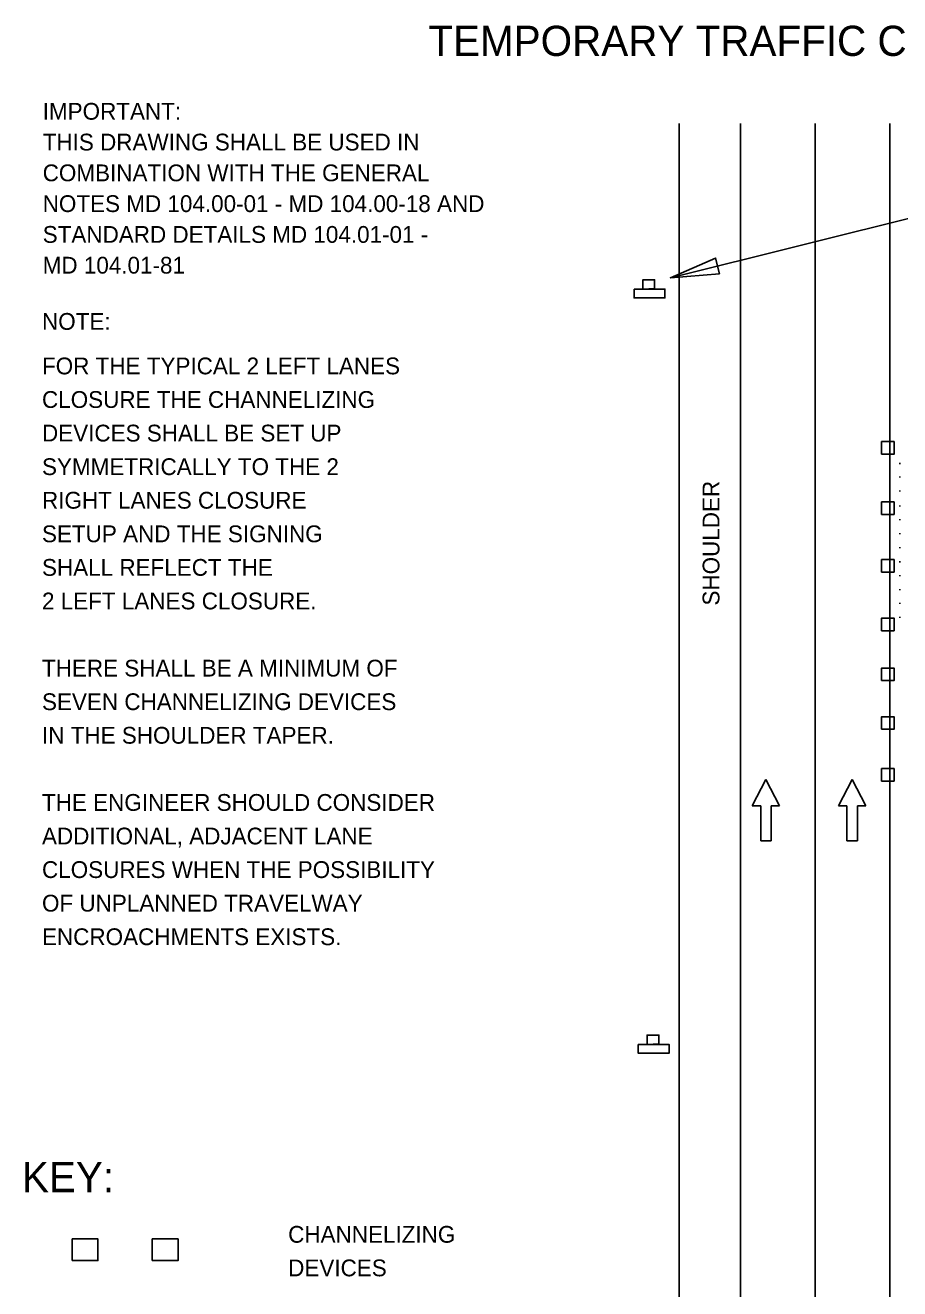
# Model space of a CAD drawing. Extents: x 1531.3 to 1538.6, y 1529.6 to 1539.7.
# Drawn here: x 1531.302 to 1534.427, y 1535.19 to 1539.705 of the extents above; entities that cross this region are included whole.
import ezdxf

# ---------------------------------------------------------------- set-up
doc = ezdxf.new("R2010")
doc.units = 0
for name, color, linetype in [('DETL-DIMS', 7, 'Continuous'), ('DETL-LINE', 7, 'Continuous'), ('DETL-NOTE', 7, 'Continuous'), ('DETL-TITL', 7, 'Continuous'), ('USER-BORD', 7, 'Continuous')]:
    doc.layers.add(name, color=color, linetype=linetype)

# ---------------------------------------------------------------- blocks, each defined once
blk = doc.blocks.new('DIR4')
at = {"layer": 'USER-BORD'}
for p, q in [((0, 0.0001), (-0.0034, -0.0048)), ((0, 0.0001), (0.0034, -0.0048)), ((-0.0034, -0.0048), (-0.0013, -0.0048)), ((-0.0013, -0.0113), (-0.0013, -0.0048)), ((0.0034, -0.0048), (0.0013, -0.0048)), ((0.0013, -0.0113), (0.0013, -0.0048)), ((-0.0001, -0.0113), (-0.0013, -0.0113)), ((-0.0001, -0.0113), (0.0001, -0.0113)), ((0.0001, -0.0113), (0.0013, -0.0113))]:
    blk.add_line(p, q, dxfattribs=at)
blk = doc.blocks.new('SIGN15')
at = {"layer": 'USER-BORD'}
for points in [[(-0.0013, 0.0018), (0.0011, 0.0019), (0.0011, 0.0037), (-0.0013, 0.0037)], [(-0.0031, 0.0018), (-0.0031, 0), (0.0032, 0), (0.0032, 0.0018)]]:
    blk.add_lwpolyline(points, close=True, dxfattribs=at)

msp = doc.modelspace()

# ---------------------------------------------------------------- linework, layer by layer
at = {"layer": 'DETL-DIMS'}
msp.add_line((1533.6072, 1538.8025), (1535.4261, 1539.2559), dxfattribs=at)
msp.add_lwpolyline([(1533.7824, 1538.8171), (1533.7685, 1538.8732), (1533.6072, 1538.8025)], close=True, dxfattribs=at)
at = {"layer": 'DETL-LINE'}
for p, q in [((1533.6384, 1539.3543), (1533.6384, 1531.4117)), ((1533.8574, 1539.3543), (1533.8574, 1531.4117)), ((1534.1244, 1539.3543), (1534.1244, 1531.4117)), ((1534.3913, 1539.3543), (1534.3913, 1531.4117))]:
    msp.add_line(p, q, dxfattribs=at)
for points in [[(1534.1244, 1539.3543), (1534.1244, 1539.2981)], [(1534.3913, 1539.3543), (1534.3913, 1539.2981)], [(1534.1244, 1538.9606), (1534.1244, 1538.9043)], [(1534.3913, 1538.9606), (1534.3913, 1538.9043)], [(1534.1244, 1538.9043), (1534.1244, 1538.8481)], [(1534.3913, 1538.9043), (1534.3913, 1538.8481)], [(1534.1244, 1538.5106), (1534.1244, 1538.4543)], [(1534.3913, 1538.5106), (1534.3913, 1538.4543)], [(1534.1244, 1538.4543), (1534.1244, 1538.3981)], [(1534.3913, 1538.4543), (1534.3913, 1538.3981)], [(1534.4267, 1538.1407), (1534.4267, 1538.1369)], [(1534.4267, 1538.0925), (1534.4267, 1538.0887)], [(1534.1244, 1538.0606), (1534.1244, 1538.0043)], [(1534.4267, 1538.0429), (1534.4267, 1538.0391)], [(1534.1244, 1538.0043), (1534.1244, 1537.9481)], [(1534.3913, 1538.0043), (1534.3913, 1537.9481)], [(1534.4267, 1537.9893), (1534.4267, 1537.9855)], [(1534.4267, 1537.9397), (1534.4267, 1537.9359)], [(1534.4267, 1537.8898), (1534.4267, 1537.886)], [(1534.4267, 1537.8402), (1534.4267, 1537.8364)], [(1534.4267, 1537.7893), (1534.4267, 1537.7855)], [(1534.4267, 1537.7397), (1534.4267, 1537.7359)], [(1534.4267, 1537.6903), (1534.4267, 1537.6865)], [(1534.4267, 1537.6407), (1534.4267, 1537.6369)], [(1534.1244, 1537.6106), (1534.1244, 1537.5543)], [(1534.3913, 1537.6106), (1534.3913, 1537.5543)], [(1534.4267, 1537.5907), (1534.4267, 1537.5869)], [(1534.1244, 1537.5543), (1534.1244, 1537.4981)], [(1534.3913, 1537.5543), (1534.3913, 1537.4981)], [(1534.1244, 1537.1606), (1534.1244, 1537.1043)], [(1534.3913, 1537.1606), (1534.3913, 1537.1043)], [(1534.1244, 1537.1043), (1534.1244, 1537.0481)], [(1534.3913, 1537.1043), (1534.3913, 1537.0481)], [(1534.1244, 1536.7106), (1534.1244, 1536.6543)], [(1534.1244, 1536.6543), (1534.1244, 1536.5981)], [(1534.1244, 1536.2606), (1534.1244, 1536.2043)], [(1534.3913, 1536.2606), (1534.3913, 1536.2043)], [(1534.1244, 1536.2043), (1534.1244, 1536.1481)], [(1534.3913, 1536.2043), (1534.3913, 1536.1481)], [(1534.1244, 1535.8106), (1534.1244, 1535.7543)], [(1534.3913, 1535.8106), (1534.3913, 1535.7543)], [(1534.1244, 1535.7543), (1534.1244, 1535.6981)], [(1534.3913, 1535.7543), (1534.3913, 1535.6981)], [(1534.1244, 1535.3606), (1534.1244, 1535.3043)], [(1534.3913, 1535.3606), (1534.3913, 1535.3043)], [(1534.1244, 1535.3043), (1534.1244, 1535.2481)], [(1534.3913, 1535.3043), (1534.3913, 1535.2481)]]:
    msp.add_lwpolyline(points, dxfattribs=at)
for points in [[(1534.3618, 1538.1721), (1534.4066, 1538.1721), (1534.4066, 1538.2169), (1534.3618, 1538.2169)], [(1534.3618, 1537.957), (1534.4066, 1537.957), (1534.4066, 1538.0018), (1534.3618, 1538.0018)], [(1534.3618, 1537.7506), (1534.4066, 1537.7506), (1534.4066, 1537.7954), (1534.3618, 1537.7954)], [(1534.3618, 1537.5414), (1534.4066, 1537.5414), (1534.4066, 1537.5862), (1534.3618, 1537.5862)], [(1534.3618, 1537.3628), (1534.4066, 1537.3628), (1534.4066, 1537.4076), (1534.3618, 1537.4076)], [(1534.3618, 1537.189), (1534.4066, 1537.189), (1534.4066, 1537.2338), (1534.3618, 1537.2338)], [(1534.3618, 1537.0038), (1534.4066, 1537.0038), (1534.4066, 1537.0486), (1534.3618, 1537.0486)], [(1531.4695, 1535.2899), (1531.4695, 1535.3677), (1531.5616, 1535.3677), (1531.5616, 1535.2899)], [(1531.7556, 1535.2899), (1531.7556, 1535.3677), (1531.8477, 1535.3677), (1531.8477, 1535.2899)]]:
    msp.add_lwpolyline(points, close=True, dxfattribs=at)

# ---------------------------------------------------------------- block references
for name, p, xscale, yscale in [('SIGN15', (1533.5315, 1538.7306), 17.523809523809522, 17.523809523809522), ('DIR4', (1533.9486, 1537.0074), 14.399999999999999, 19.2), ('DIR4', (1534.2568, 1537.0074), 14.399999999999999, 19.2), ('SIGN15', (1533.5466, 1536.0311), 17.523809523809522, 17.523809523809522)]:
    msp.add_blockref(name, p, dxfattribs=dict(at, xscale=xscale, yscale=yscale))

# ---------------------------------------------------------------- texts
at = {"layer": 'DETL-NOTE'}
for s, p in [('IMPORTANT:', (1531.3641, 1539.3675)), ('THIS DRAWING SHALL BE USED IN', (1531.3641, 1539.2575)), ('COMBINATION WITH THE GENERAL', (1531.3641, 1539.1475)), ('NOTES MD 104.00-01 - MD 104.00-18 AND', (1531.3641, 1539.0375)), ('STANDARD DETAILS MD 104.01-01 -', (1531.3641, 1538.9275)), ('MD 104.01-81', (1531.3641, 1538.8175)), ('NOTE:', (1531.3616, 1538.6166)), ('FOR THE TYPICAL 2 LEFT LANES', (1531.3616, 1538.4575)), ('CLOSURE THE CHANNELIZING', (1531.3616, 1538.3375)), ('DEVICES SHALL BE SET UP', (1531.3616, 1538.2175)), ('SYMMETRICALLY TO THE 2', (1531.3616, 1538.0975)), ('RIGHT LANES CLOSURE', (1531.3616, 1537.9775)), ('SETUP AND THE SIGNING', (1531.3616, 1537.8575)), ('SHALL REFLECT THE', (1531.3616, 1537.7375)), ('2 LEFT LANES CLOSURE.', (1531.3616, 1537.6175)), ('THERE SHALL BE A MINIMUM OF ', (1531.3616, 1537.3775)), ('SEVEN CHANNELIZING DEVICES ', (1531.3616, 1537.2575)), ('IN THE SHOULDER TAPER.', (1531.3616, 1537.1375)), ('THE ENGINEER SHOULD CONSIDER', (1531.3616, 1536.8975)), ('ADDITIONAL, ADJACENT LANE', (1531.3616, 1536.7775)), ('CLOSURES WHEN THE POSSIBILITY', (1531.3616, 1536.6575)), ('OF UNPLANNED TRAVELWAY', (1531.3616, 1536.5375)), ('ENCROACHMENTS EXISTS.', (1531.3616, 1536.4175)), ('CHANNELIZING', (1532.2413, 1535.354)), ('DEVICES', (1532.2413, 1535.234))]:
    msp.add_text(s, height=0.06, dxfattribs=at).set_placement(p)
msp.add_text('SHOULDER', height=0.06, rotation=90, dxfattribs=at).set_placement((1533.7824, 1537.6311))
at = {"layer": 'DETL-TITL'}
for s, p in [('TEMPORARY TRAFFIC CONTROL TYPICAL APPLICATION', (1532.7424, 1539.5954)), ('KEY:', (1531.29, 1535.5347))]:
    msp.add_text(s, height=0.108, dxfattribs=at).set_placement(p)

doc.saveas('drawing.dxf')
